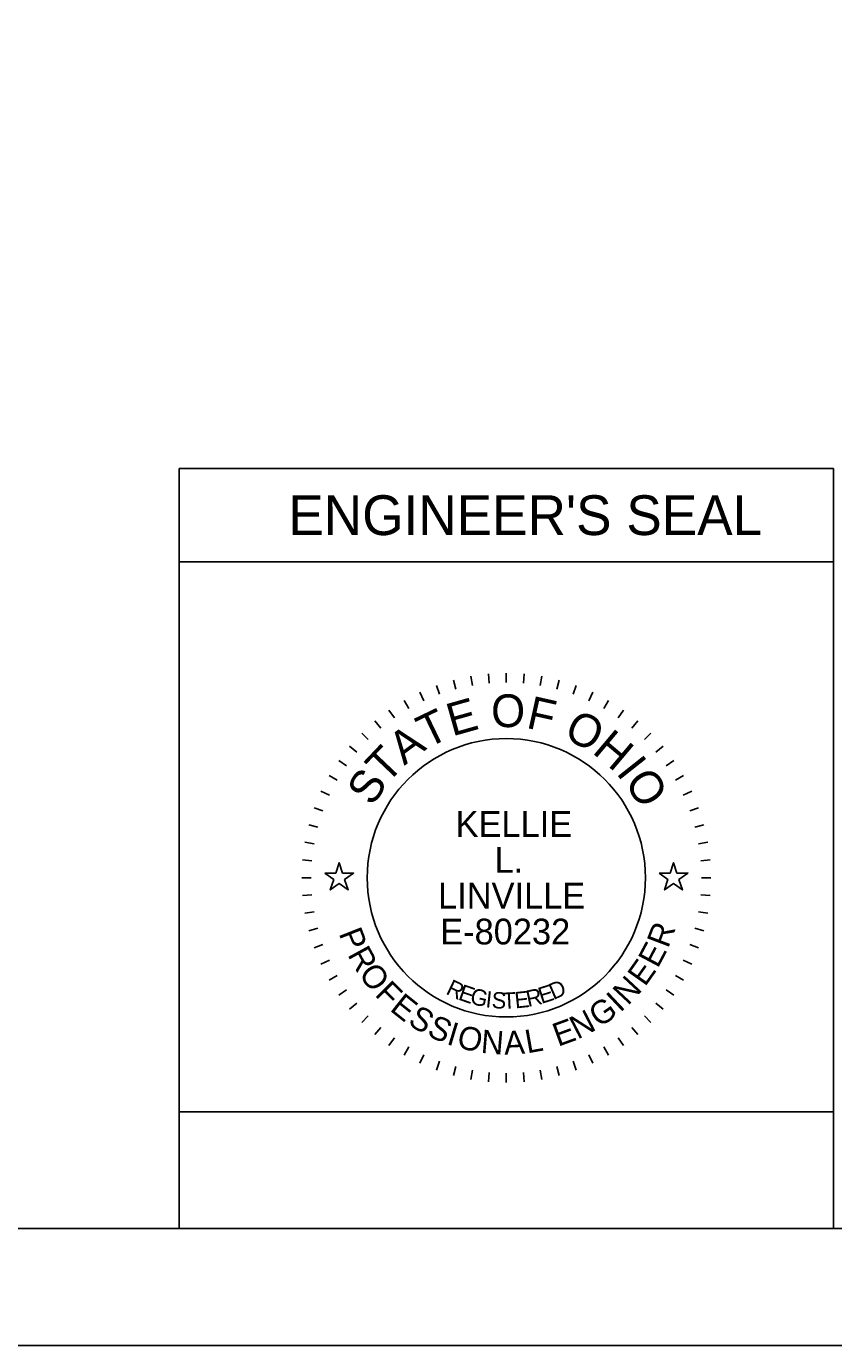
# Model space of a CAD drawing. Extents: x 0 to 34, y 0 to 22.
# Drawn here: x 6.7 to 10.15, y 0 to 5.64 of the extents above; entities that cross this region are included whole.
import ezdxf

# ---------------------------------------------------------------- set-up
doc = ezdxf.new("R2010")
doc.units = 0
for name, color, linetype in [('Default', 7, 'Continuous'), ('SH_Border', 7, 'Continuous'), ('SH_Cut_Line', 7, 'Continuous'), ('SH_Data', 7, 'Continuous')]:
    doc.layers.add(name, color=color, linetype=linetype)

msp = doc.modelspace()

# ---------------------------------------------------------------- linework, layer by layer
at = {"layer": 'Default'}
for points in [[(7.9736, 2.02), (8.0205, 2.02), (8.035, 2.0645), (8.0495, 2.02), (8.0964, 2.02), (8.0585, 1.9924), (8.073, 1.9478), (8.035, 1.9754), (7.997, 1.9478), (8.0115, 1.9924)], [(9.4036, 2.02), (9.4505, 2.02), (9.465, 2.0645), (9.4795, 2.02), (9.5264, 2.02), (9.4885, 1.9924), (9.503, 1.9478), (9.465, 1.9754), (9.427, 1.9478), (9.4415, 1.9924)]]:
    msp.add_lwpolyline(points, close=True, dxfattribs=at)
at = {"layer": 'SH_Border'}
msp.add_lwpolyline([(1.5, 21.5), (33.5, 21.5), (33.5, 0.5), (1.5, 0.5)], close=True, dxfattribs=at)
at = {"layer": 'SH_Cut_Line'}
msp.add_lwpolyline([(0, 0), (34, 0), (34, 22), (0, 22)], close=True, dxfattribs=at)
at = {"layer": 'SH_Data'}
for p, q in [((10.15, 3.75), (7.35, 3.75)), ((7.35, 3.75), (7.35, 0.5)), ((10.15, 0.5), (10.15, 3.75)), ((10.15, 3.35), (7.35, 3.35)), ((8.4507, 2.8222), (8.4644, 2.7846)), ((8.5235, 2.8452), (8.5339, 2.8065)), ((8.5981, 2.8617), (8.605, 2.8223)), ((8.6737, 2.8717), (8.6772, 2.8318)), ((8.75, 2.875), (8.75, 2.835)), ((8.8263, 2.8717), (8.8228, 2.8318)), ((8.9019, 2.8617), (8.895, 2.8223)), ((8.9765, 2.8452), (8.9661, 2.8065)), ((9.0493, 2.8222), (9.0356, 2.7846)), ((8.3802, 2.793), (8.3971, 2.7568)), ((9.1198, 2.793), (9.1029, 2.7568)), ((8.2481, 2.7168), (8.2711, 2.684)), ((8.3125, 2.7578), (8.3325, 2.7231)), ((9.1875, 2.7578), (9.1675, 2.7231)), ((9.2519, 2.7168), (9.2289, 2.684)), ((8.1876, 2.6703), (8.2133, 2.6396)), ((9.3124, 2.6703), (9.2867, 2.6396)), ((8.1313, 2.6187), (8.1596, 2.5904)), ((9.3687, 2.6187), (9.3404, 2.5904)), ((8.0797, 2.5624), (8.1104, 2.5367)), ((9.4203, 2.5624), (9.3896, 2.5367)), ((8.0332, 2.5019), (8.066, 2.4789)), ((9.4668, 2.5019), (9.434, 2.4789)), ((7.9922, 2.4375), (8.0269, 2.4175)), ((9.5078, 2.4375), (9.4731, 2.4175)), ((7.957, 2.3698), (7.9932, 2.3529)), ((9.543, 2.3698), (9.5068, 2.3529)), ((7.9278, 2.2993), (7.9654, 2.2856)), ((9.5722, 2.2993), (9.5346, 2.2856)), ((7.9048, 2.2265), (7.9435, 2.2161)), ((9.5952, 2.2265), (9.5565, 2.2161)), ((7.8883, 2.1519), (7.9277, 2.145)), ((9.6117, 2.1519), (9.5723, 2.145)), ((7.8783, 2.0763), (7.9182, 2.0728)), ((9.6217, 2.0763), (9.5818, 2.0728)), ((7.875, 2), (7.915, 2)), ((9.625, 2), (9.585, 2)), ((7.8783, 1.9237), (7.9182, 1.9272)), ((9.6217, 1.9237), (9.5818, 1.9272)), ((7.8883, 1.8481), (7.9277, 1.855)), ((9.6117, 1.8481), (9.5723, 1.855)), ((7.9048, 1.7735), (7.9435, 1.7839)), ((9.5952, 1.7735), (9.5565, 1.7839)), ((7.9278, 1.7007), (7.9654, 1.7144)), ((9.5722, 1.7007), (9.5346, 1.7144)), ((7.957, 1.6302), (7.9932, 1.6471)), ((9.543, 1.6302), (9.5068, 1.6471)), ((7.9922, 1.5625), (8.0269, 1.5825)), ((9.5078, 1.5625), (9.4731, 1.5825)), ((8.0332, 1.4981), (8.066, 1.5211)), ((9.4668, 1.4981), (9.434, 1.5211)), ((8.0797, 1.4376), (8.1104, 1.4633)), ((9.4203, 1.4376), (9.3896, 1.4633)), ((8.1313, 1.3813), (8.1596, 1.4096)), ((8.1876, 1.3297), (8.2133, 1.3604)), ((9.3124, 1.3297), (9.2867, 1.3604)), ((9.3687, 1.3813), (9.3404, 1.4096)), ((8.2481, 1.2832), (8.2711, 1.316)), ((9.2519, 1.2832), (9.2289, 1.316)), ((8.3125, 1.2422), (8.3325, 1.2769)), ((8.3802, 1.207), (8.3971, 1.2432)), ((9.1198, 1.207), (9.1029, 1.2432)), ((9.1875, 1.2422), (9.1675, 1.2769)), ((8.4507, 1.1778), (8.4644, 1.2154)), ((8.5235, 1.1548), (8.5339, 1.1935)), ((8.9765, 1.1548), (8.9661, 1.1935)), ((9.0493, 1.1778), (9.0356, 1.2154)), ((8.5981, 1.1383), (8.605, 1.1777)), ((8.6737, 1.1283), (8.6772, 1.1682)), ((8.75, 1.125), (8.75, 1.165)), ((8.8263, 1.1283), (8.8228, 1.1682)), ((8.9019, 1.1383), (8.895, 1.1777)), ((10.15, 0.5), (7.35, 0.5))]:
    msp.add_line(p, q, dxfattribs=at)
msp.add_lwpolyline([(10.15, 0.5), (10.15, 1), (7.35, 1), (7.35, 0.5)], close=True, dxfattribs=at)
msp.add_circle((8.75, 2), 0.595, dxfattribs=at)

# ---------------------------------------------------------------- texts
for s, height, p in [("ENGINEER'S SEAL", 0.17, (7.8176, 3.465)), ('KELLIE', 0.11, (8.5328, 2.1749)), ('L.', 0.11, (8.6995, 2.0216)), ('LINVILLE', 0.11, (8.458, 1.8684)), ('E-80232', 0.11, (8.4672, 1.7151))]:
    msp.add_text(s, height=height, dxfattribs=at).set_placement(p)
for s, height, rotation, p in [('E', 0.14, 15.7571, (8.5184, 2.6038)), ('O', 0.14, 359.7812, (8.6847, 2.6443)), ('F', 0.14, 347.4362, (8.8311, 2.6417)), ('T', 0.14, 25.7167, (8.4116, 2.5518)), ('O', 0.14, 332.2586, (8.9898, 2.6015)), ('A', 0.14, 36.4747, (8.3134, 2.4781)), ('H', 0.14, 319.9136, (9.1132, 2.5361)), ('T', 0.14, 46.4344, (8.2383, 2.3964)), ('I', 0.14, 308.367, (9.2165, 2.4483)), ('S', 0.14, 57.1924, (8.1781, 2.3014)), ('O', 0.14, 303.1491, (9.2521, 2.4089)), ('R', 0.1, 69.2322, (9.4419, 1.6954)), ('P', 0.1, 291.494, (8.0323, 1.7621)), ('R', 0.1, 298.7311, (8.069, 1.6717)), ('E', 0.1, 61.9951, (9.3976, 1.6098)), ('E', 0.1, 54.758, (9.3433, 1.5314)), ('O', 0.1, 306.4666, (8.1155, 1.5883)), ('N', 0.1, 47.0224, (9.2702, 1.4508)), ('F', 0.1, 314.7068, (8.1843, 1.4983)), ('R', 0.07, 334.487, (8.4875, 1.5051)), ('E', 0.07, 341.04, (8.5406, 1.4801)), ('G', 0.07, 347.4752, (8.5914, 1.4618)), ('R', 0.07, 11.9184, (8.8425, 1.4474)), ('E', 0.07, 17.6836, (8.8998, 1.4602)), ('D', 0.07, 23.3052, (8.951, 1.477)), ('E', 0.1, 321.4393, (8.2478, 1.4348)), ('I', 0.07, 353.7858, (8.6591, 1.4468)), ('S', 0.07, 356.8926, (8.6858, 1.4429)), ('T', 0.07, 3.0061, (8.7357, 1.4387)), ('E', 0.07, 6.0117, (8.7889, 1.4412)), ('G', 0.1, 35.0469, (9.1481, 1.357)), ('I', 0.1, 43.287, (9.2368, 1.4214)), ('S', 0.1, 328.6764, (8.3243, 1.3752)), ('N', 0.1, 27.3113, (9.0545, 1.3075)), ('S', 0.1, 335.9134, (8.4064, 1.3266)), ('I', 0.1, 343.1505, (8.4906, 1.2897)), ('O', 0.1, 346.8859, (8.5339, 1.2751)), ('E', 0.1, 20.0742, (8.9712, 1.277)), ('N', 0.1, 355.1261, (8.6388, 1.2517)), ('A', 0.1, 2.8617, (8.7423, 1.2437)), ('L', 0.1, 10.0987, (8.8394, 1.249))]:
    msp.add_text(s, height=height, rotation=rotation, dxfattribs=at).set_placement(p)

doc.saveas('drawing.dxf')
